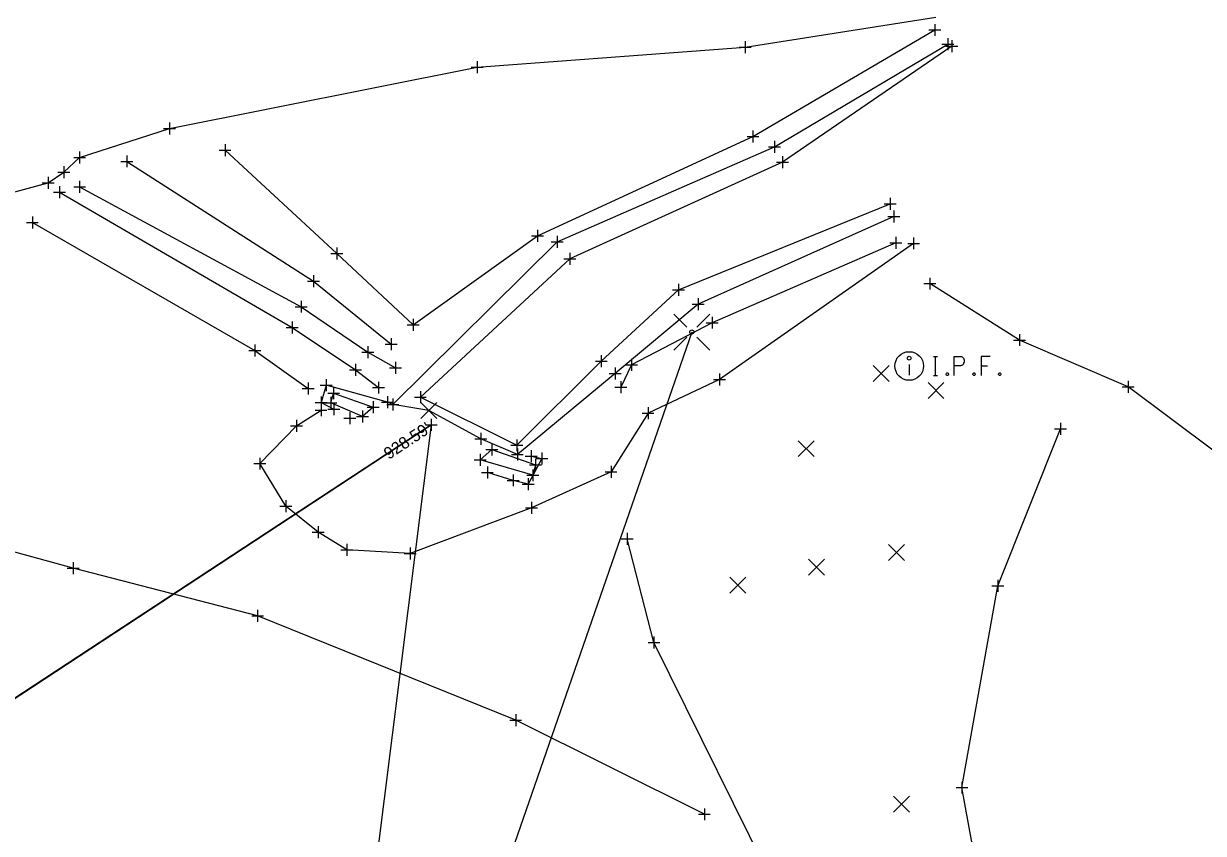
# Model space of a CAD drawing. Extents: x 2331247 to 2333939, y 279314 to 282014.
# Drawn here: x 2332783.1 to 2332882.1, y 280578.4 to 280646.3 of the extents above; entities that cross this region are included whole.
import ezdxf

# ---------------------------------------------------------------- set-up
doc = ezdxf.new("R2010")
doc.units = 0
for name, color, linetype in [('DR_X_Headwall', 7, 'Continuous'), ('DR_X_Storm_Sewer', 7, 'Continuous'), ('HY_X_Water_Edge', 7, 'Continuous'), ('SC_Scratch1', 7, 'Continuous'), ('Stream 1', 7, 'Continuous'), ('SV_Observation', 7, 'Continuous'), ('SV_X_Break_Lines', 7, 'Continuous'), ('SV_X_Control_Cells_Found', 7, 'Continuous'), ('SV_X_Random_Point', 7, 'Continuous'), ('UNT', 7, 'Continuous')]:
    doc.layers.add(name, color=color, linetype=linetype)

msp = doc.modelspace()

# ---------------------------------------------------------------- linework, layer by layer
msp.add_lwpolyline([(2332817.325, 280612.657), (2332607.421, 280474.916)])
at = {"layer": 'DR_X_Headwall'}
for points in [[(2332811.547, 280613.359), (2332808.893, 280614.512), (2332809.135, 280615.298), (2332812.438, 280614.149)], [(2332822.395, 280610.579), (2332826.054, 280609.307), (2332825.828, 280608.428), (2332821.423, 280609.729)]]:
    msp.add_lwpolyline(points, close=True, dxfattribs=at)
at = {"layer": 'DR_X_Storm_Sewer'}
msp.add_line((2332607.421, 280474.916), (2332817.325, 280612.657), dxfattribs=at)
at = {"layer": 'HY_X_Water_Edge'}
for points in [[(2332814.104, 280614.356), (2332827.864, 280627.994), (2332846.105, 280635.959), (2332860.625, 280644.562)], [(2332856.107, 280630.128), (2332839.692, 280622.767), (2332832.735, 280616.952), (2332824.536, 280610.167), (2332821.477, 280611.479)]]:
    msp.add_lwpolyline(points, dxfattribs=at)
at = {"layer": 'SC_Scratch1'}
for p, q in [((2332816.825, 280612.657), (2332817.825, 280612.657)), ((2332817.325, 280613.157), (2332817.325, 280612.157)), ((2332817.325, 280612.657), (2332817.325, 280612.657))]:
    msp.add_line(p, q, dxfattribs=at)
at = {"layer": 'Stream 1'}
for p, q in [((2332859.546, 280646.249), (2332859.546, 280645.249)), ((2332859.046, 280645.749), (2332860.046, 280645.749)), ((2332859.546, 280645.749), (2332859.546, 280645.749)), ((2332860.625, 280645.062), (2332860.625, 280644.062)), ((2332843.145, 280644.302), (2332844.145, 280644.302)), ((2332843.645, 280644.802), (2332843.645, 280643.802)), ((2332843.645, 280644.302), (2332843.645, 280644.302)), ((2332860.125, 280644.562), (2332861.125, 280644.562)), ((2332860.468, 280644.398), (2332861.468, 280644.398)), ((2332860.625, 280644.562), (2332860.625, 280644.562)), ((2332860.968, 280644.898), (2332860.968, 280643.898)), ((2332860.968, 280644.398), (2332860.968, 280644.398)), ((2332821.178, 280643.126), (2332821.178, 280642.126)), ((2332820.678, 280642.626), (2332821.678, 280642.626)), ((2332821.178, 280642.626), (2332821.178, 280642.626)), ((2332794.88, 280637.501), (2332795.88, 280637.501)), ((2332795.38, 280638.001), (2332795.38, 280637.001)), ((2332795.38, 280637.501), (2332795.38, 280637.501)), ((2332844.292, 280637.322), (2332844.292, 280636.322)), ((2332800.028, 280636.184), (2332800.028, 280635.184)), ((2332843.792, 280636.822), (2332844.792, 280636.822)), ((2332844.292, 280636.822), (2332844.292, 280636.822)), ((2332846.105, 280636.459), (2332846.105, 280635.459)), ((2332787.84, 280635.558), (2332787.84, 280634.558)), ((2332791.804, 280635.241), (2332791.804, 280634.241)), ((2332799.528, 280635.684), (2332800.528, 280635.684)), ((2332800.028, 280635.684), (2332800.028, 280635.684)), ((2332845.605, 280635.959), (2332846.605, 280635.959)), ((2332846.105, 280635.959), (2332846.105, 280635.959)), ((2332846.756, 280635.176), (2332846.756, 280634.176)), ((2332786.504, 280634.327), (2332786.504, 280633.327)), ((2332787.34, 280635.058), (2332788.34, 280635.058)), ((2332787.84, 280635.058), (2332787.84, 280635.058)), ((2332791.304, 280634.741), (2332792.304, 280634.741)), ((2332791.804, 280634.741), (2332791.804, 280634.741)), ((2332846.256, 280634.676), (2332847.256, 280634.676)), ((2332846.756, 280634.676), (2332846.756, 280634.676)), ((2332785.195, 280633.439), (2332785.195, 280632.439)), ((2332786.004, 280633.827), (2332787.004, 280633.827)), ((2332786.504, 280633.827), (2332786.504, 280633.827)), ((2332784.695, 280632.939), (2332785.695, 280632.939)), ((2332785.195, 280632.939), (2332785.195, 280632.939)), ((2332785.648, 280632.153), (2332786.648, 280632.153)), ((2332786.148, 280632.653), (2332786.148, 280631.653)), ((2332786.148, 280632.153), (2332786.148, 280632.153)), ((2332787.341, 280632.598), (2332788.341, 280632.598)), ((2332787.841, 280633.098), (2332787.841, 280632.098)), ((2332787.841, 280632.598), (2332787.841, 280632.598)), ((2332855.287, 280631.18), (2332856.287, 280631.18)), ((2332855.787, 280631.68), (2332855.787, 280630.68)), ((2332855.787, 280631.18), (2332855.787, 280631.18)), ((2332856.107, 280630.628), (2332856.107, 280629.628)), ((2332783.375, 280629.625), (2332784.375, 280629.625)), ((2332783.875, 280630.125), (2332783.875, 280629.125)), ((2332783.875, 280629.625), (2332783.875, 280629.625)), ((2332855.607, 280630.128), (2332856.607, 280630.128)), ((2332856.107, 280630.128), (2332856.107, 280630.128)), ((2332825.716, 280628.498), (2332826.716, 280628.498)), ((2332826.216, 280628.998), (2332826.216, 280627.998)), ((2332826.216, 280628.498), (2332826.216, 280628.498)), ((2332827.864, 280628.494), (2332827.864, 280627.494)), ((2332856.27, 280628.403), (2332856.27, 280627.403)), ((2332857.762, 280628.369), (2332857.762, 280627.369)), ((2332809.41, 280627.511), (2332809.41, 280626.511)), ((2332827.364, 280627.994), (2332828.364, 280627.994)), ((2332827.864, 280627.994), (2332827.864, 280627.994)), ((2332855.77, 280627.903), (2332856.77, 280627.903)), ((2332856.27, 280627.903), (2332856.27, 280627.903)), ((2332857.262, 280627.869), (2332858.262, 280627.869)), ((2332857.762, 280627.869), (2332857.762, 280627.869)), ((2332808.91, 280627.011), (2332809.91, 280627.011)), ((2332809.41, 280627.011), (2332809.41, 280627.011)), ((2332828.441, 280626.573), (2332829.441, 280626.573)), ((2332828.941, 280627.073), (2332828.941, 280626.073)), ((2332828.941, 280626.573), (2332828.941, 280626.573)), ((2332806.955, 280624.692), (2332807.955, 280624.692)), ((2332807.455, 280625.192), (2332807.455, 280624.192)), ((2332807.455, 280624.692), (2332807.455, 280624.692)), ((2332838.053, 280624.476), (2332838.053, 280623.476)), ((2332858.608, 280624.49), (2332859.608, 280624.49)), ((2332859.108, 280624.99), (2332859.108, 280623.99)), ((2332859.108, 280624.49), (2332859.108, 280624.49)), ((2332837.553, 280623.976), (2332838.553, 280623.976)), ((2332838.053, 280623.976), (2332838.053, 280623.976)), ((2332839.692, 280623.267), (2332839.692, 280622.267)), ((2332805.902, 280622.559), (2332806.902, 280622.559)), ((2332806.402, 280623.059), (2332806.402, 280622.059)), ((2332806.402, 280622.559), (2332806.402, 280622.559)), ((2332839.192, 280622.767), (2332840.192, 280622.767)), ((2332839.692, 280622.767), (2332839.692, 280622.767)), ((2332805.653, 280621.311), (2332805.653, 280620.311)), ((2332815.803, 280621.549), (2332815.803, 280620.549)), ((2332840.861, 280621.72), (2332840.861, 280620.72)), ((2332805.153, 280620.811), (2332806.153, 280620.811)), ((2332805.653, 280620.811), (2332805.653, 280620.811)), ((2332815.303, 280621.049), (2332816.303, 280621.049)), ((2332815.803, 280621.049), (2332815.803, 280621.049)), ((2332840.361, 280621.22), (2332841.361, 280621.22)), ((2332840.861, 280621.22), (2332840.861, 280621.22)), ((2332802.533, 280619.39), (2332802.533, 280618.39)), ((2332813.464, 280619.426), (2332814.464, 280619.426)), ((2332813.964, 280619.926), (2332813.964, 280618.926)), ((2332813.964, 280619.426), (2332813.964, 280619.426)), ((2332866.133, 280619.766), (2332867.133, 280619.766)), ((2332866.633, 280620.266), (2332866.633, 280619.266)), ((2332866.633, 280619.766), (2332866.633, 280619.766)), ((2332802.033, 280618.89), (2332803.033, 280618.89)), ((2332802.533, 280618.89), (2332802.533, 280618.89)), ((2332811.512, 280618.759), (2332812.512, 280618.759)), ((2332812.012, 280619.259), (2332812.012, 280618.259)), ((2332812.012, 280618.759), (2332812.012, 280618.759)), ((2332831.575, 280618.501), (2332831.575, 280617.501)), ((2332810.962, 280617.77), (2332810.962, 280616.77)), ((2332813.818, 280617.427), (2332814.818, 280617.427)), ((2332814.318, 280617.927), (2332814.318, 280616.927)), ((2332814.318, 280617.427), (2332814.318, 280617.427)), ((2332831.075, 280618.001), (2332832.075, 280618.001)), ((2332831.575, 280618.001), (2332831.575, 280618.001)), ((2332832.735, 280617.452), (2332832.735, 280616.452)), ((2332833.61, 280617.695), (2332834.61, 280617.695)), ((2332834.11, 280618.195), (2332834.11, 280617.195)), ((2332834.11, 280617.695), (2332834.11, 280617.695)), ((2332808.519, 280616.493), (2332808.519, 280615.493)), ((2332810.462, 280617.27), (2332811.462, 280617.27)), ((2332810.962, 280617.27), (2332810.962, 280617.27)), ((2332832.235, 280616.952), (2332833.235, 280616.952)), ((2332832.735, 280616.952), (2332832.735, 280616.952)), ((2332840.981, 280616.462), (2332841.981, 280616.462)), ((2332841.481, 280616.962), (2332841.481, 280615.962)), ((2332841.481, 280616.462), (2332841.481, 280616.462)), ((2332875.756, 280616.343), (2332875.756, 280615.343)), ((2332806.493, 280615.699), (2332807.493, 280615.699)), ((2332806.993, 280616.199), (2332806.993, 280615.199)), ((2332806.993, 280615.699), (2332806.993, 280615.699)), ((2332808.019, 280615.993), (2332809.019, 280615.993)), ((2332808.519, 280615.993), (2332808.519, 280615.993)), ((2332809.135, 280615.798), (2332809.135, 280614.798)), ((2332812.393, 280615.775), (2332813.393, 280615.775)), ((2332812.893, 280616.275), (2332812.893, 280615.275)), ((2332812.893, 280615.775), (2332812.893, 280615.775)), ((2332816.403, 280615.467), (2332816.403, 280614.467)), ((2332832.72, 280615.808), (2332833.72, 280615.808)), ((2332833.22, 280616.308), (2332833.22, 280615.308)), ((2332833.22, 280615.808), (2332833.22, 280615.808)), ((2332875.256, 280615.843), (2332876.256, 280615.843)), ((2332875.756, 280615.843), (2332875.756, 280615.843)), ((2332807.592, 280614.538), (2332808.592, 280614.538)), ((2332808.078, 280614.392), (2332808.078, 280613.392)), ((2332808.092, 280615.038), (2332808.092, 280614.038)), ((2332808.092, 280614.538), (2332808.092, 280614.538)), ((2332808.393, 280614.512), (2332809.393, 280614.512)), ((2332808.635, 280615.298), (2332809.635, 280615.298)), ((2332808.893, 280615.012), (2332808.893, 280614.012)), ((2332808.893, 280614.512), (2332808.893, 280614.512)), ((2332809.135, 280615.298), (2332809.135, 280615.298)), ((2332809.151, 280614.471), (2332809.151, 280613.471)), ((2332812.438, 280614.649), (2332812.438, 280613.649)), ((2332813.161, 280614.55), (2332814.161, 280614.55)), ((2332813.604, 280614.356), (2332814.604, 280614.356)), ((2332813.661, 280615.05), (2332813.661, 280614.05)), ((2332813.661, 280614.55), (2332813.661, 280614.55)), ((2332814.104, 280614.856), (2332814.104, 280613.856)), ((2332814.104, 280614.356), (2332814.104, 280614.356)), ((2332815.903, 280614.967), (2332816.903, 280614.967)), ((2332816.403, 280614.967), (2332816.403, 280614.967)), ((2332807.578, 280613.892), (2332808.578, 280613.892)), ((2332808.078, 280613.892), (2332808.078, 280613.892)), ((2332808.651, 280613.971), (2332809.651, 280613.971)), ((2332809.151, 280613.971), (2332809.151, 280613.971)), ((2332810.498, 280613.706), (2332810.498, 280612.706)), ((2332811.047, 280613.359), (2332812.047, 280613.359)), ((2332811.547, 280613.859), (2332811.547, 280612.859)), ((2332811.547, 280613.359), (2332811.547, 280613.359)), ((2332811.938, 280614.149), (2332812.938, 280614.149)), ((2332812.438, 280614.149), (2332812.438, 280614.149)), ((2332834.99, 280613.636), (2332835.99, 280613.636)), ((2332835.49, 280614.136), (2332835.49, 280613.136)), ((2332835.49, 280613.636), (2332835.49, 280613.636)), ((2332805.524, 280612.567), (2332806.524, 280612.567)), ((2332806.024, 280613.067), (2332806.024, 280612.067)), ((2332806.024, 280612.567), (2332806.024, 280612.567)), ((2332809.998, 280613.206), (2332810.998, 280613.206)), ((2332810.498, 280613.206), (2332810.498, 280613.206)), ((2332870.073, 280612.821), (2332870.073, 280611.821)), ((2332820.977, 280611.479), (2332821.977, 280611.479)), ((2332821.477, 280611.979), (2332821.477, 280610.979)), ((2332821.477, 280611.479), (2332821.477, 280611.479)), ((2332824.489, 280611.44), (2332824.489, 280610.44)), ((2332869.573, 280612.321), (2332870.573, 280612.321)), ((2332870.073, 280612.321), (2332870.073, 280612.321)), ((2332821.895, 280610.579), (2332822.895, 280610.579)), ((2332822.395, 280611.079), (2332822.395, 280610.079)), ((2332822.395, 280610.579), (2332822.395, 280610.579)), ((2332823.989, 280610.94), (2332824.989, 280610.94)), ((2332824.489, 280610.94), (2332824.489, 280610.94)), ((2332824.536, 280610.667), (2332824.536, 280609.667)), ((2332825.696, 280610.533), (2332825.696, 280609.533)), ((2332802.45, 280609.405), (2332803.45, 280609.405)), ((2332802.95, 280609.905), (2332802.95, 280608.905)), ((2332802.95, 280609.405), (2332802.95, 280609.405)), ((2332820.923, 280609.729), (2332821.923, 280609.729)), ((2332821.423, 280610.229), (2332821.423, 280609.229)), ((2332821.423, 280609.729), (2332821.423, 280609.729)), ((2332824.036, 280610.167), (2332825.036, 280610.167)), ((2332824.536, 280610.167), (2332824.536, 280610.167)), ((2332825.196, 280610.033), (2332826.196, 280610.033)), ((2332825.696, 280610.033), (2332825.696, 280610.033)), ((2332826.054, 280609.807), (2332826.054, 280608.807)), ((2332826.088, 280609.829), (2332827.088, 280609.829)), ((2332826.588, 280610.329), (2332826.588, 280609.329)), ((2332826.588, 280609.829), (2332826.588, 280609.829)), ((2332821.523, 280608.663), (2332822.523, 280608.663)), ((2332822.023, 280609.163), (2332822.023, 280608.163)), ((2332822.023, 280608.663), (2332822.023, 280608.663)), ((2332824.187, 280608.506), (2332824.187, 280607.506)), ((2332825.328, 280608.428), (2332826.328, 280608.428)), ((2332825.554, 280609.307), (2332826.554, 280609.307)), ((2332825.828, 280608.928), (2332825.828, 280607.928)), ((2332825.828, 280608.428), (2332825.828, 280608.428)), ((2332826.054, 280609.307), (2332826.054, 280609.307)), ((2332831.89, 280608.73), (2332832.89, 280608.73)), ((2332832.39, 280609.23), (2332832.39, 280608.23)), ((2332832.39, 280608.73), (2332832.39, 280608.73)), ((2332823.687, 280608.006), (2332824.687, 280608.006)), ((2332824.187, 280608.006), (2332824.187, 280608.006)), ((2332824.936, 280607.694), (2332825.936, 280607.694)), ((2332825.436, 280608.194), (2332825.436, 280607.194)), ((2332825.436, 280607.694), (2332825.436, 280607.694)), ((2332804.637, 280605.851), (2332805.637, 280605.851)), ((2332805.137, 280606.351), (2332805.137, 280605.351)), ((2332805.137, 280605.851), (2332805.137, 280605.851)), ((2332825.226, 280605.706), (2332826.226, 280605.706)), ((2332825.726, 280606.206), (2332825.726, 280605.206)), ((2332825.726, 280605.706), (2332825.726, 280605.706)), ((2332807.342, 280603.667), (2332808.342, 280603.667)), ((2332807.842, 280604.167), (2332807.842, 280603.167)), ((2332807.842, 280603.667), (2332807.842, 280603.667)), ((2332833.741, 280603.612), (2332833.741, 280602.612)), ((2332810.249, 280602.672), (2332810.249, 280601.672)), ((2332833.241, 280603.112), (2332834.241, 280603.112)), ((2332833.741, 280603.112), (2332833.741, 280603.112)), ((2332809.749, 280602.172), (2332810.749, 280602.172)), ((2332810.249, 280602.172), (2332810.249, 280602.172)), ((2332815.042, 280601.884), (2332816.042, 280601.884)), ((2332815.542, 280602.384), (2332815.542, 280601.384)), ((2332815.542, 280601.884), (2332815.542, 280601.884)), ((2332786.787, 280600.654), (2332787.787, 280600.654)), ((2332787.287, 280601.154), (2332787.287, 280600.154)), ((2332787.287, 280600.654), (2332787.287, 280600.654)), ((2332864.81, 280599.663), (2332864.81, 280598.663)), ((2332864.31, 280599.163), (2332865.31, 280599.163)), ((2332864.81, 280599.163), (2332864.81, 280599.163)), ((2332802.264, 280596.643), (2332803.264, 280596.643)), ((2332802.764, 280597.143), (2332802.764, 280596.143)), ((2332802.764, 280596.643), (2332802.764, 280596.643)), ((2332835.991, 280594.918), (2332835.991, 280593.918)), ((2332835.491, 280594.418), (2332836.491, 280594.418)), ((2332835.991, 280594.418), (2332835.991, 280594.418)), ((2332823.898, 280587.902), (2332824.898, 280587.902)), ((2332824.398, 280588.402), (2332824.398, 280587.402)), ((2332824.398, 280587.902), (2332824.398, 280587.902)), ((2332861.814, 280582.751), (2332861.814, 280581.751)), ((2332861.314, 280582.251), (2332862.314, 280582.251)), ((2332861.814, 280582.251), (2332861.814, 280582.251)), ((2332839.713, 280580.015), (2332840.713, 280580.015)), ((2332840.213, 280580.515), (2332840.213, 280579.515)), ((2332840.213, 280580.015), (2332840.213, 280580.015))]:
    msp.add_line(p, q, dxfattribs=at)
at = {"layer": 'SV_Observation'}
for p in [(2332839.165, 280620.437), (2332817.325, 280612.657)]:
    msp.add_line(p, (2332806.391, 280525.905), dxfattribs=at)
at = {"layer": 'SV_X_Break_Lines'}
for points in [[(2332506.585, 280703.497), (2332531.37, 280692.168), (2332556.659, 280687.235), (2332588.418, 280676.816), (2332608.921, 280672.874), (2332642.353, 280666.14), (2332663.081, 280660.516), (2332688.585, 280653.888), (2332712.54, 280648.123), (2332737.327, 280641.167), (2332759.605, 280635), (2332774.985, 280633.373), (2332782.408, 280632.184), (2332785.195, 280632.939), (2332786.504, 280633.827), (2332787.84, 280635.058), (2332795.38, 280637.501), (2332821.178, 280642.626), (2332843.645, 280644.302), (2332859.627, 280646.819)], [(2332800.028, 280635.684), (2332809.41, 280627.011), (2332815.803, 280621.049), (2332826.216, 280628.498), (2332844.292, 280636.822), (2332859.546, 280645.749)], [(2332860.968, 280644.398), (2332846.756, 280634.676), (2332828.941, 280626.573), (2332816.403, 280614.967), (2332824.489, 280610.94), (2332831.575, 280618.001), (2332838.053, 280623.976), (2332855.787, 280631.18)], [(2332791.804, 280634.741), (2332807.455, 280624.692), (2332813.964, 280619.426)], [(2332786.148, 280632.153), (2332805.653, 280620.811), (2332810.962, 280617.27), (2332812.893, 280615.775)], [(2332787.841, 280632.598), (2332806.402, 280622.559), (2332812.012, 280618.759), (2332814.318, 280617.427)], [(2332783.875, 280629.625), (2332802.533, 280618.89), (2332806.993, 280615.699)], [(2332857.762, 280627.869), (2332841.481, 280616.462), (2332835.49, 280613.636), (2332832.39, 280608.73), (2332825.726, 280605.706), (2332815.542, 280601.884), (2332810.249, 280602.172), (2332807.842, 280603.667), (2332805.137, 280605.851), (2332802.95, 280609.405), (2332806.024, 280612.567), (2332808.078, 280613.892)], [(2332856.27, 280627.903), (2332840.861, 280621.22), (2332834.11, 280617.695), (2332833.22, 280615.808)], [(2332927.2, 280580.83), (2332912.442, 280589.855), (2332897.369, 280599.664), (2332875.756, 280615.843), (2332866.633, 280619.766), (2332859.108, 280624.49)], [(2332840.213, 280580.015), (2332824.398, 280587.902), (2332802.764, 280596.643), (2332787.287, 280600.654), (2332769.948, 280605.406), (2332745.159, 280615.785)], [(2332821.477, 280611.479), (2332817.125, 280613.856), (2332814.104, 280614.356), (2332813.661, 280614.55), (2332808.519, 280615.993), (2332808.092, 280614.538), (2332809.151, 280613.971)], [(2332880.257, 280508.463), (2332878.642, 280517.02), (2332876.5, 280533.33), (2332870.505, 280548.016), (2332864.755, 280566.128), (2332861.814, 280582.251), (2332864.81, 280599.163), (2332870.073, 280612.321)], [(2332825.696, 280610.033), (2332826.588, 280609.829), (2332825.436, 280607.694), (2332824.187, 280608.006), (2332822.023, 280608.663)], [(2332874.996, 280508.837), (2332873.63, 280516.161), (2332870.404, 280531.942), (2332864.031, 280543.991), (2332857.057, 280559.056), (2332846.683, 280572.783), (2332835.991, 280594.418), (2332833.741, 280603.112)]]:
    msp.add_lwpolyline(points, dxfattribs=at)
at = {"layer": 'SV_X_Control_Cells_Found'}
for p, q in [((2332837.655, 280621.941), (2332838.748, 280620.847)), ((2332839.581, 280620.847), (2332840.673, 280621.941)), ((2332837.655, 280618.922), (2332838.748, 280620.016)), ((2332839.581, 280620.016), (2332840.673, 280618.922))]:
    msp.add_line(p, q, dxfattribs=at)
msp.add_circle((2332839.165, 280620.437), 0.17, dxfattribs=at)
at = {"layer": 'SV_X_Random_Point'}
for p, q in [((2332854.378, 280616.295), (2332855.712, 280617.63)), ((2332854.378, 280617.63), (2332855.712, 280616.295)), ((2332858.967, 280614.862), (2332860.301, 280616.197)), ((2332858.967, 280616.197), (2332860.301, 280614.862)), ((2332816.458, 280613.188), (2332817.792, 280614.523)), ((2332816.458, 280614.523), (2332817.792, 280613.188)), ((2332848.078, 280609.994), (2332849.412, 280611.329)), ((2332848.078, 280611.329), (2332849.412, 280609.994)), ((2332855.663, 280601.292), (2332856.997, 280602.627)), ((2332855.663, 280602.627), (2332856.997, 280601.292)), ((2332848.948, 280600.062), (2332850.282, 280601.397)), ((2332848.948, 280601.397), (2332850.282, 280600.062)), ((2332842.352, 280598.552), (2332843.686, 280599.886)), ((2332842.352, 280599.886), (2332843.686, 280598.552)), ((2332856.077, 280580.21), (2332857.411, 280581.545)), ((2332856.077, 280581.545), (2332857.411, 280580.21))]:
    msp.add_line(p, q, dxfattribs=at)
at = {"layer": 'UNT'}
msp.add_line((2332857.388, 280617.706), (2332857.388, 280616.822), dxfattribs=at)
for points in [[(2332859.418, 280618.389), (2332859.771, 280618.389)], [(2332859.595, 280616.789), (2332859.595, 280618.389)], [(2332861.16, 280616.789), (2332861.16, 280618.389), (2332861.689, 280618.389), (2332861.744, 280618.376), (2332861.821, 280618.351), (2332861.855, 280618.326), (2332861.887, 280618.301), (2332861.932, 280618.238), (2332861.965, 280618.175), (2332861.987, 280618.074), (2332861.987, 280617.923), (2332861.976, 280617.872), (2332861.954, 280617.797), (2332861.91, 280617.709), (2332861.865, 280617.671), (2332861.832, 280617.646), (2332861.777, 280617.62), (2332861.689, 280617.608), (2332861.16, 280617.608)], [(2332864.169, 280618.389), (2332863.409, 280618.389), (2332863.409, 280616.789)], [(2332863.409, 280617.608), (2332863.949, 280617.608)], [(2332859.418, 280616.789), (2332859.771, 280616.789)], [(2332860.554, 280617.003), (2332860.609, 280617.003), (2332860.642, 280616.978), (2332860.675, 280616.928), (2332860.675, 280616.864), (2332860.642, 280616.814), (2332860.609, 280616.789), (2332860.554, 280616.789), (2332860.521, 280616.814), (2332860.488, 280616.864), (2332860.488, 280616.928), (2332860.521, 280616.978), (2332860.554, 280617.003)], [(2332862.802, 280617.003), (2332862.858, 280617.003), (2332862.891, 280616.978), (2332862.924, 280616.928), (2332862.924, 280616.864), (2332862.891, 280616.814), (2332862.858, 280616.789), (2332862.802, 280616.789), (2332862.769, 280616.814), (2332862.736, 280616.864), (2332862.736, 280616.928), (2332862.769, 280616.978), (2332862.802, 280617.003)], [(2332864.952, 280617.003), (2332865.007, 280617.003), (2332865.04, 280616.978), (2332865.073, 280616.928), (2332865.073, 280616.864), (2332865.04, 280616.814), (2332865.007, 280616.789), (2332864.952, 280616.789), (2332864.919, 280616.814), (2332864.886, 280616.864), (2332864.886, 280616.928), (2332864.919, 280616.978), (2332864.952, 280617.003)]]:
    msp.add_lwpolyline(points, dxfattribs=at)
for centre, radius in [((2332857.388, 280617.589), 1.2), ((2332857.388, 280618.241), 0.16)]:
    msp.add_circle(centre, radius, dxfattribs=at)

# ---------------------------------------------------------------- texts
at = {"layer": 'SC_Scratch1'}
msp.add_text("928.59'", height=1, rotation=33.27328, dxfattribs=at).set_placement((2332813.755, 280609.716))

doc.saveas('drawing.dxf')
